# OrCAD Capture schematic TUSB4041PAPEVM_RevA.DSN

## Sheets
1 P1_4041: size C; title: TUSB4041PAPEVM; rev: A.0; company: Texas Instruments, CIS/ICP; note: GAGGIA.DSN
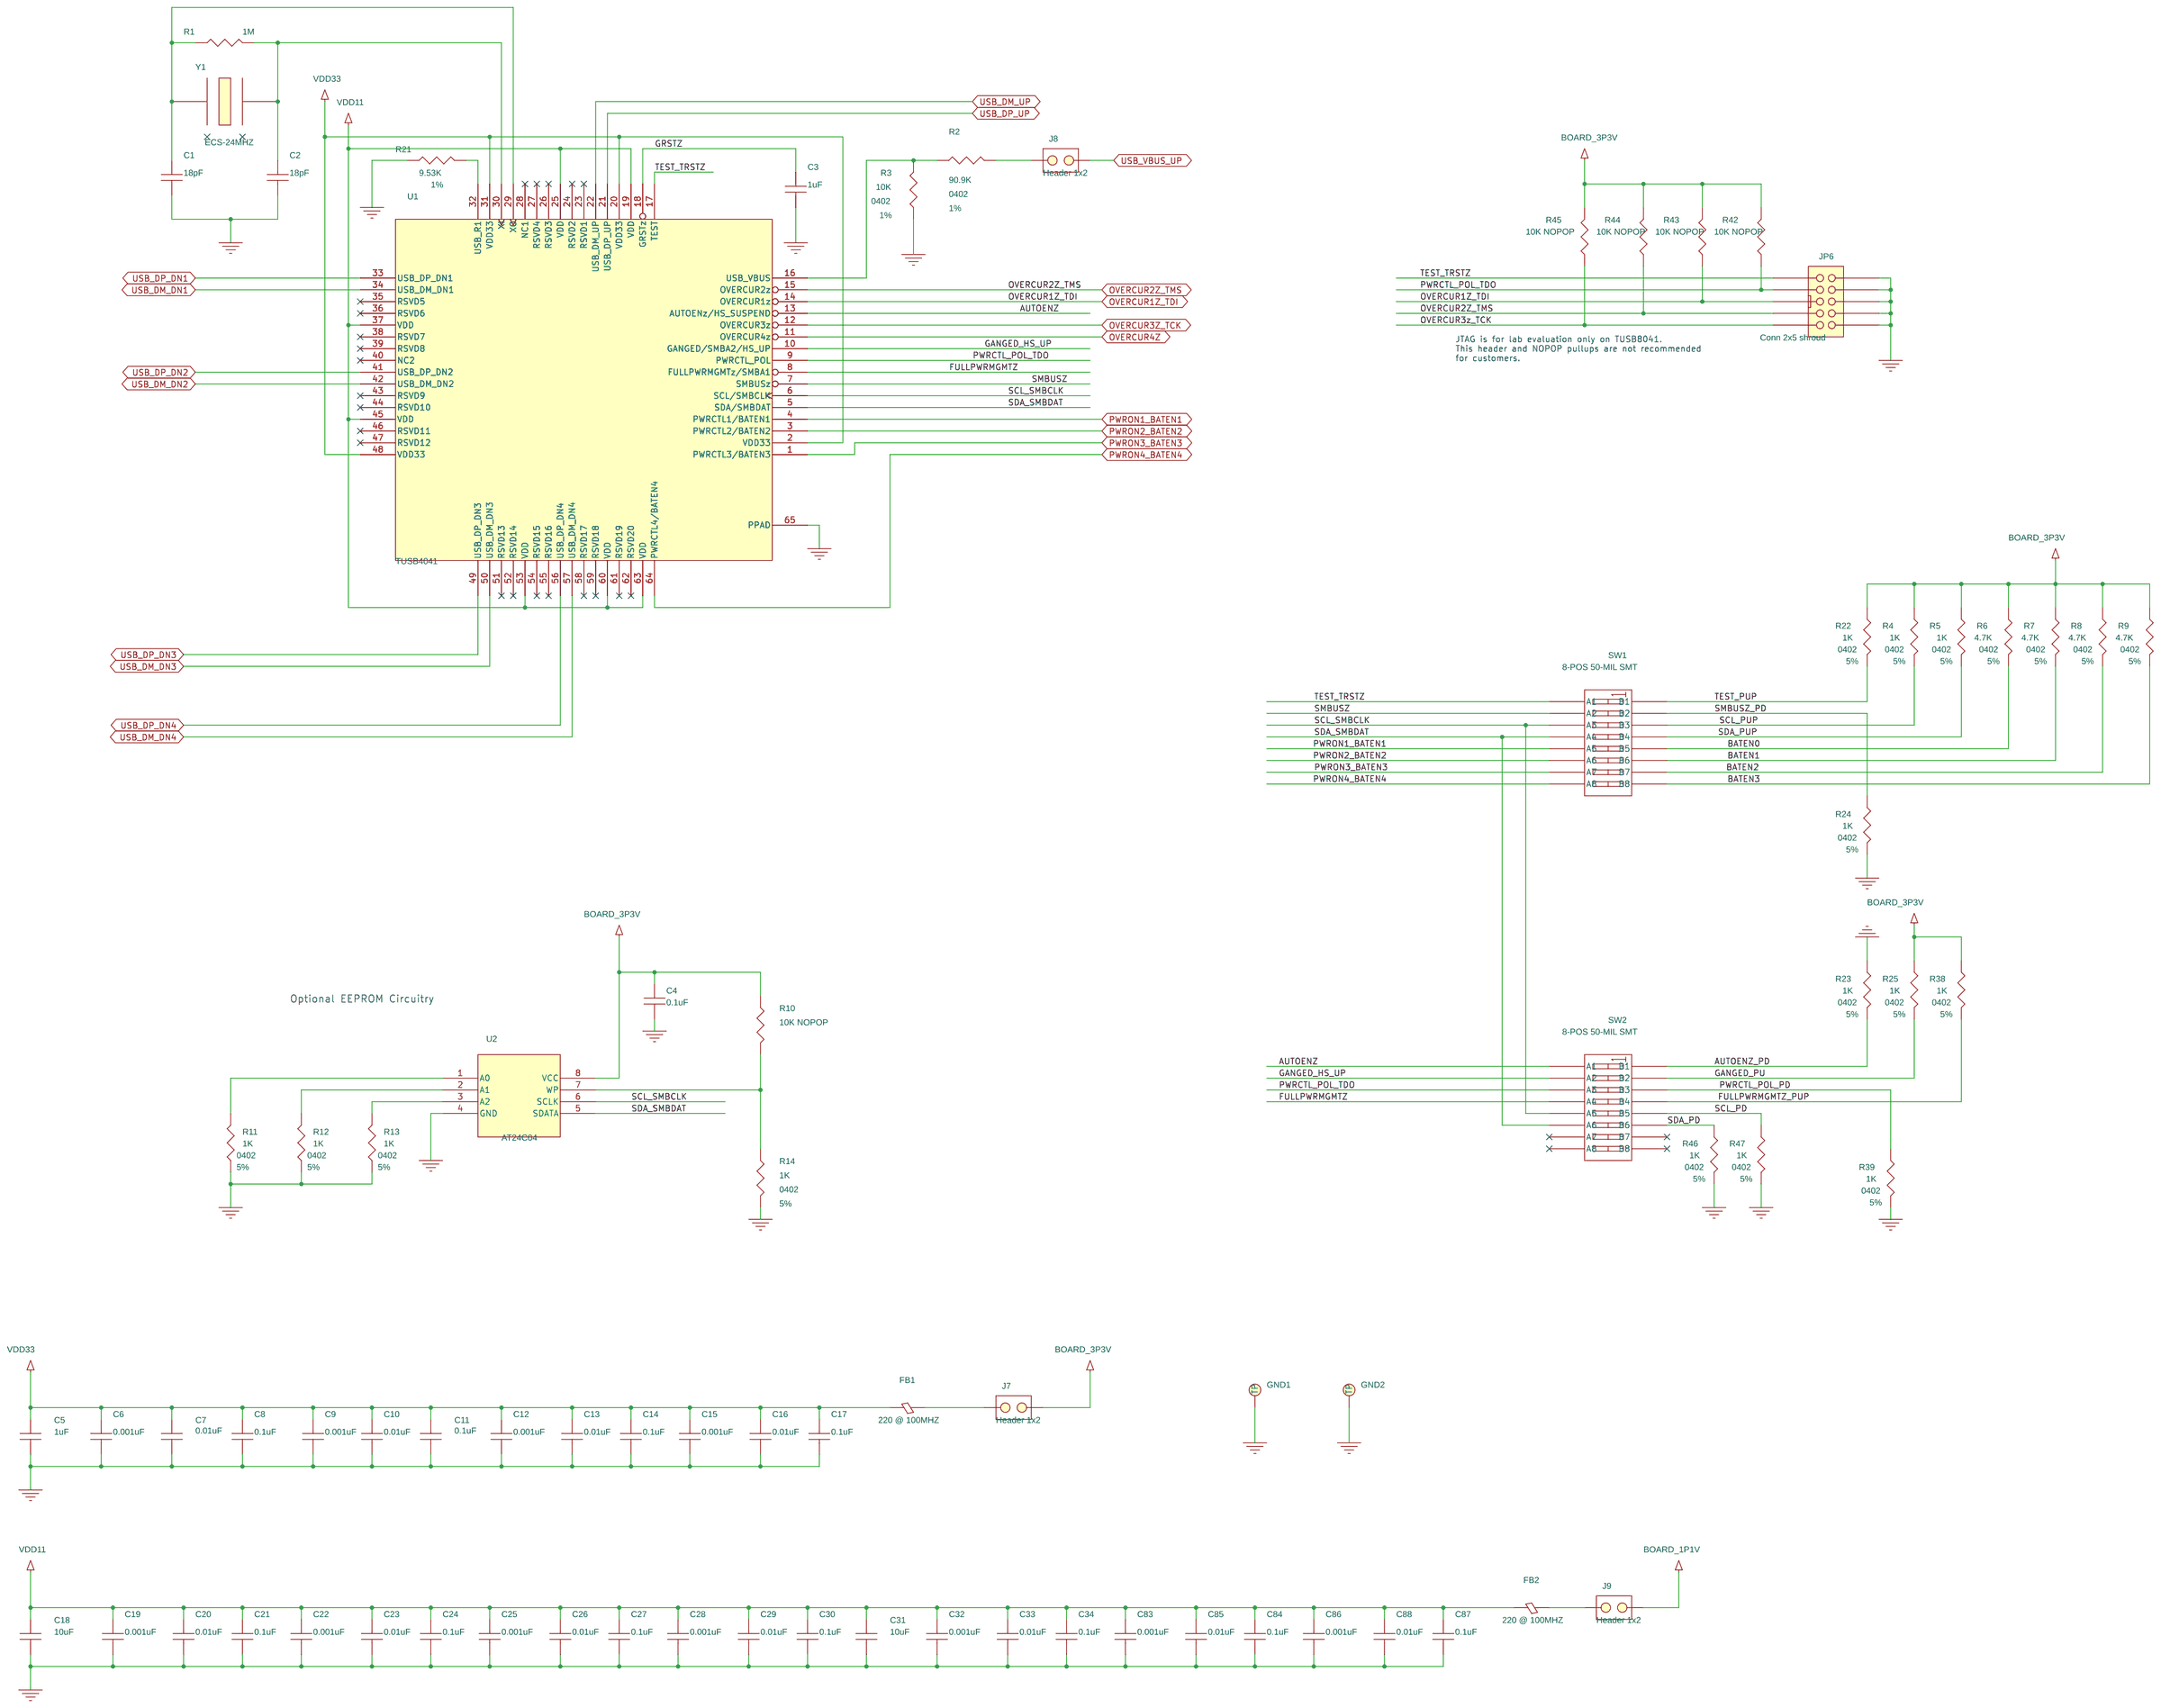
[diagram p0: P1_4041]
2 P2_CONNECTORS: size C; title: TUSB4041PAPEVM: USB2 CONNECTORS
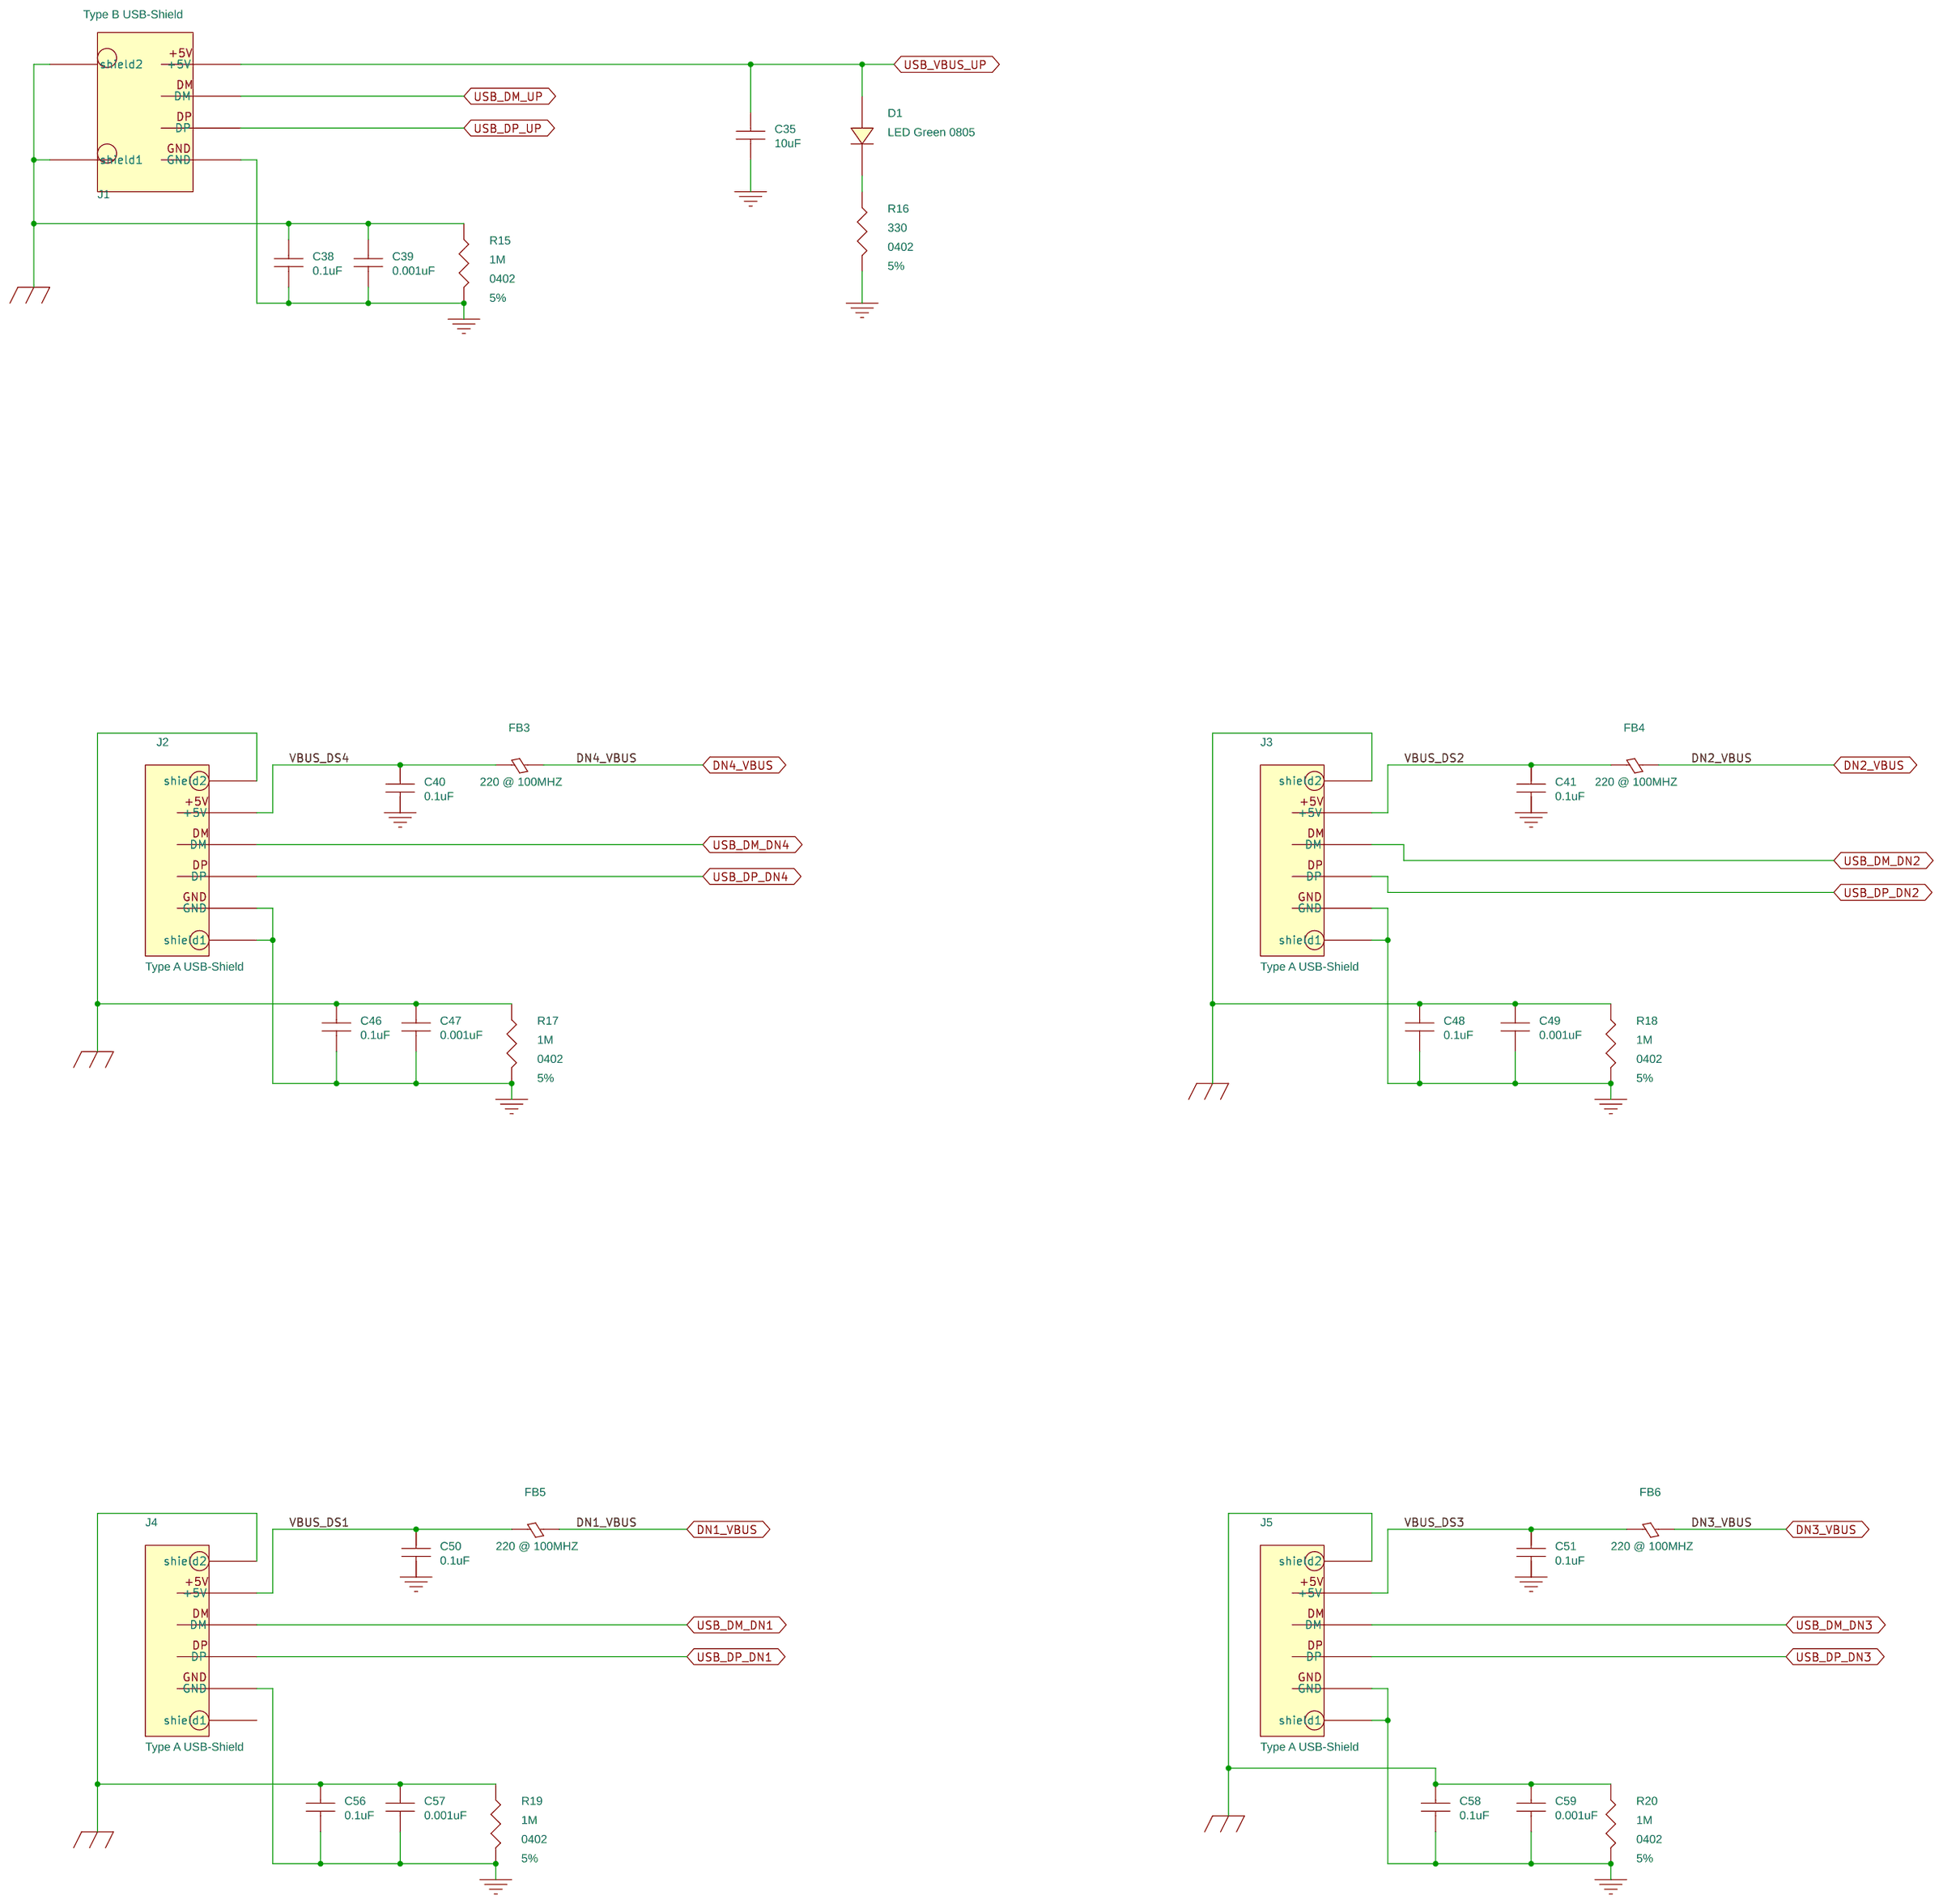
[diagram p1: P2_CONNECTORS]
3 P3_POWER: size C; title: TUSB4041PAPEVM:POWER
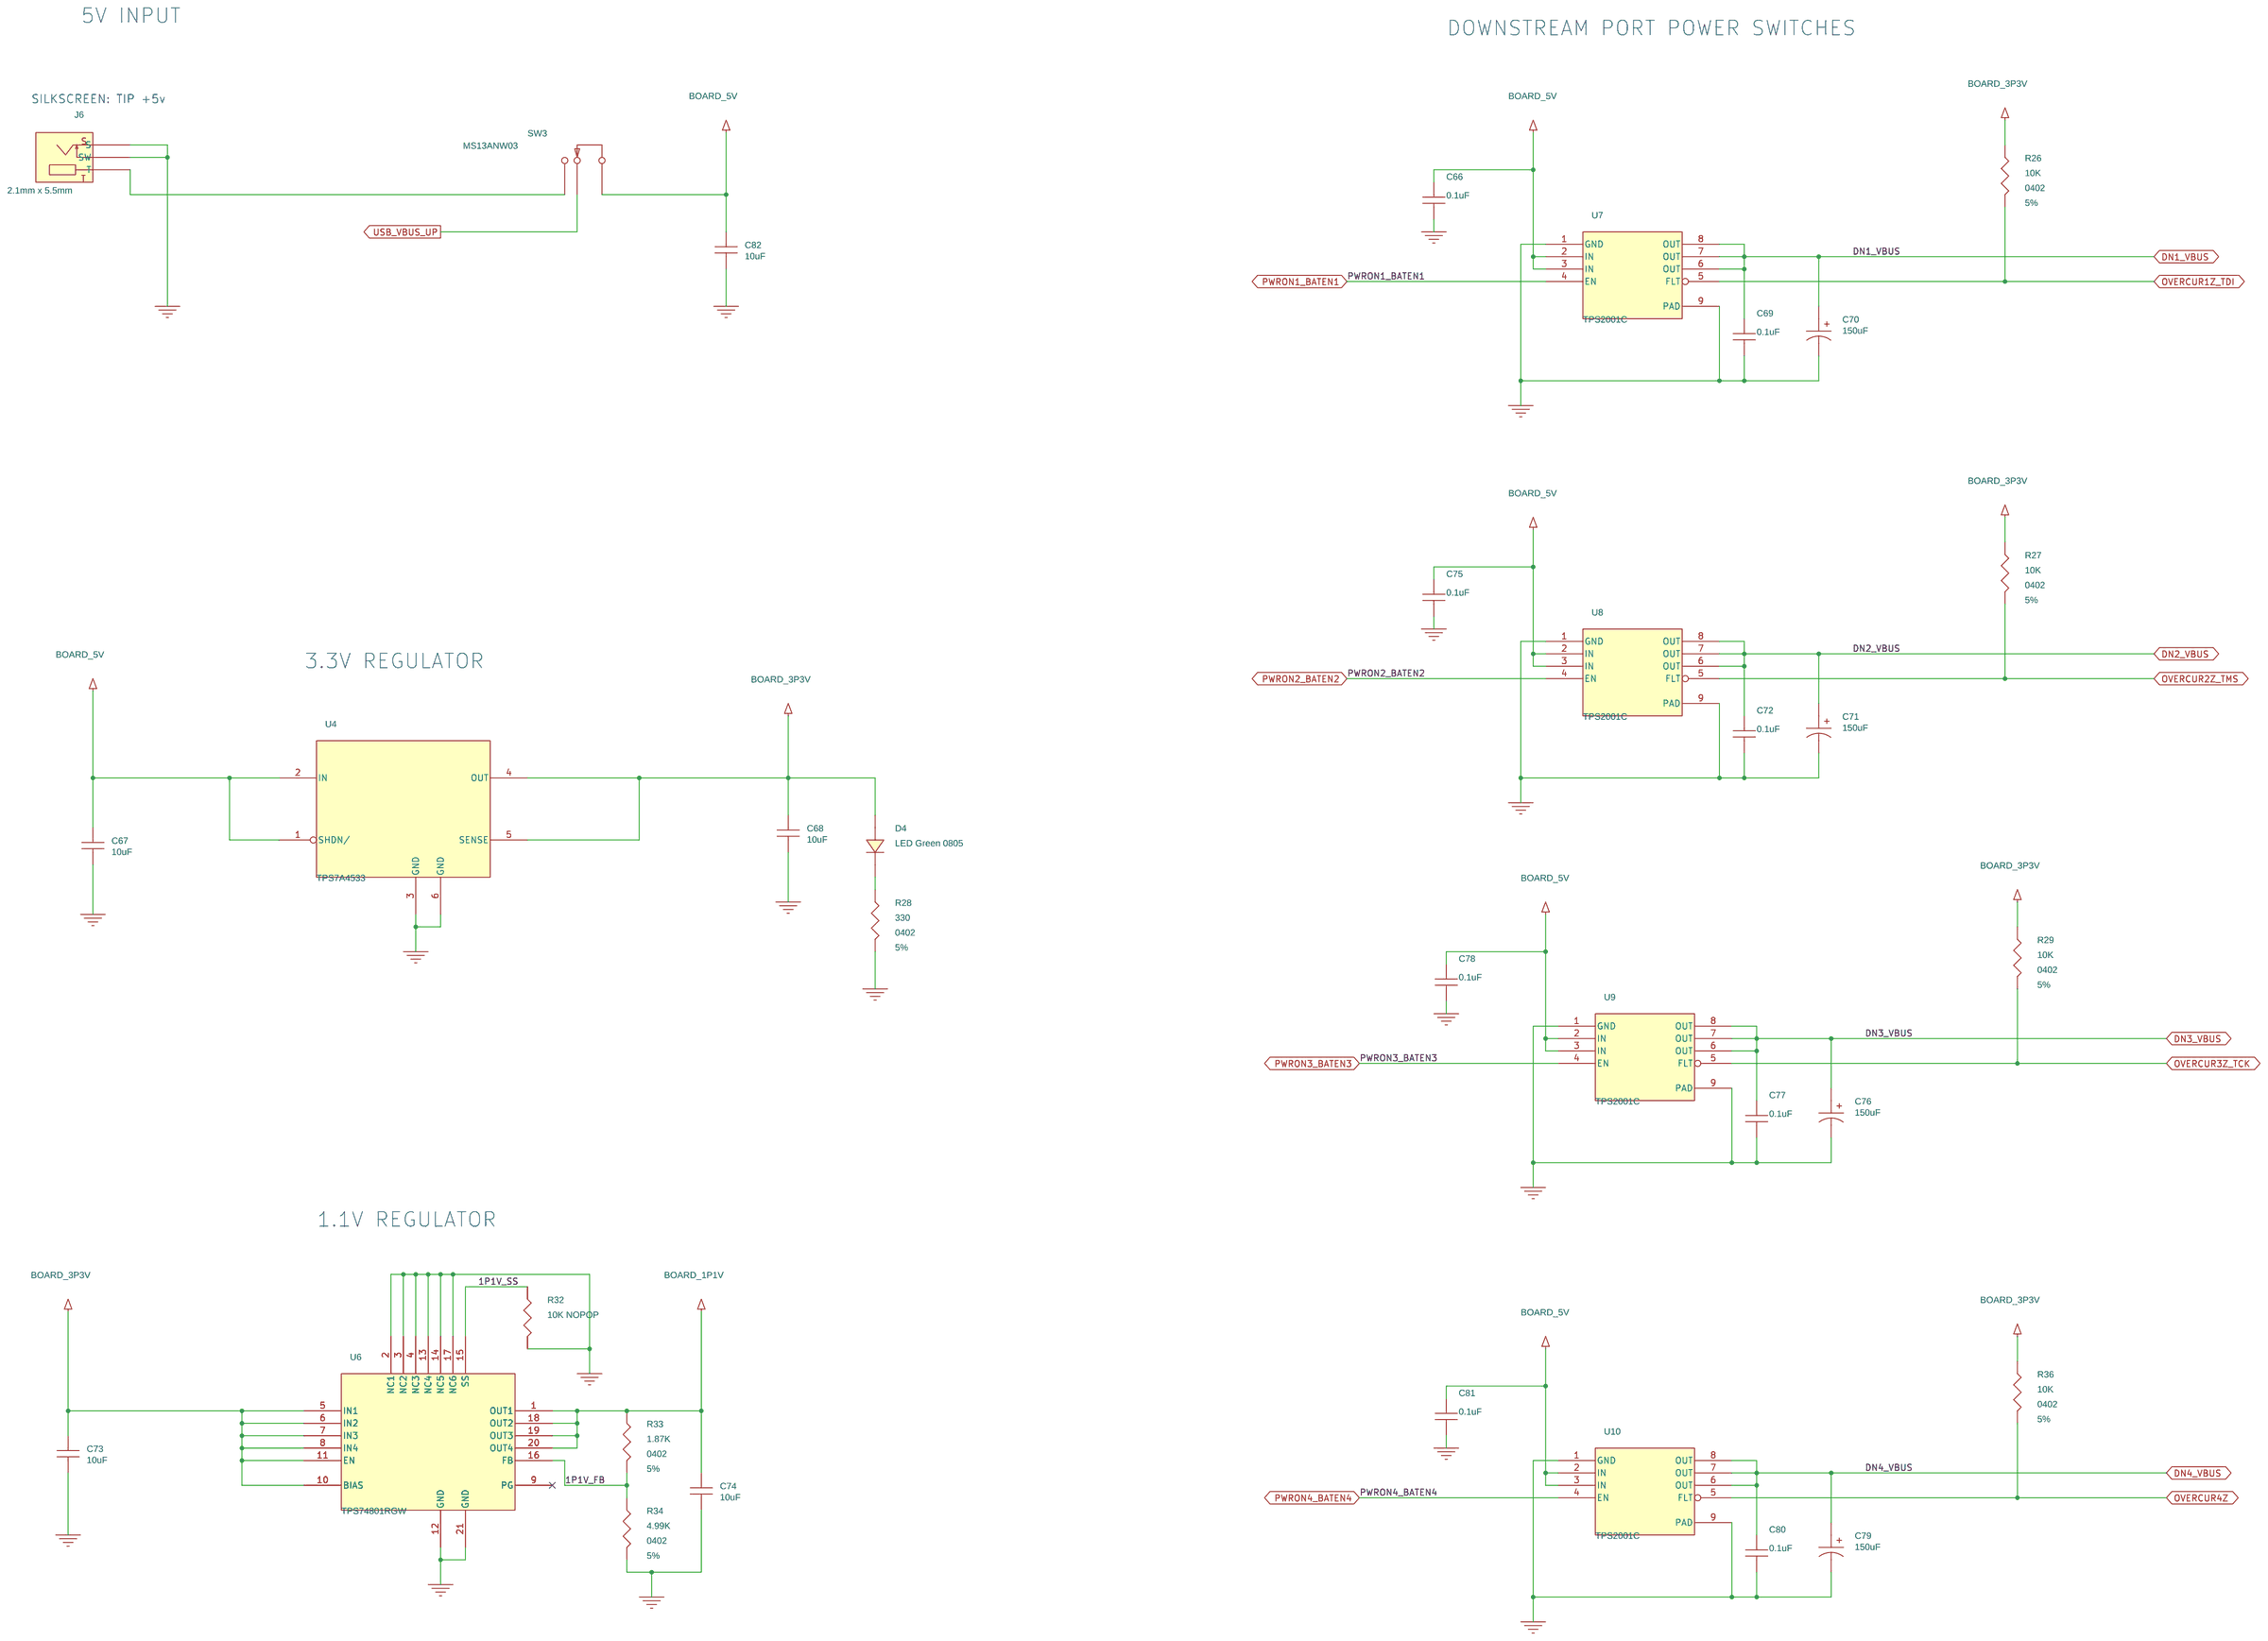
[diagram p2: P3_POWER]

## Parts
sheet P1_4041
C1  18pF  [0402]
C2  18pF  [0402]
C3  1uF  [0402]
C4  0.1uF  [0402]
C5  1uF  [0805]
C6  0.001uF  [0201]
C7  0.01uF  [0201]
C8  0.1uF  [0201]
C9  0.001uF  [0201]
C10  0.01uF  [0201]
C11  0.1uF  [0201]
C12  0.001uF  [0201]
C13  0.01uF  [0201]
C14  0.1uF  [0201]
C15  0.001uF  [0201]
C16  0.01uF  [0201]
C17  0.1uF  [0201]
C18  10uF  [1206]
C19  0.001uF  [0201]
C20  0.01uF  [0201]
C21  0.1uF  [0201]
C22  0.001uF  [0201]
C23  0.01uF  [0201]
C24  0.1uF  [0201]
C25  0.001uF  [0201]
C26  0.01uF  [0201]
C27  0.1uF  [0201]
C28  0.001uF  [0201]
C29  0.01uF  [0201]
C30  0.1uF  [0201]
C31  10uF  [1206]
C32  0.001uF  [0201]
C33  0.01uF  [0201]
C34  0.1uF  [0201]
C83  0.001uF  [0201]
C84  0.1uF  [0201]
C85  0.01uF  [0201]
C86  0.001uF  [0201]
C87  0.1uF  [0201]
C88  0.01uF  [0201]
FB1  220 @ 100MHZ  [0603]
FB2  220 @ 100MHZ  [0603]
GND1  TEST POINT  [testloop]
GND2  TEST POINT  [testloop]
J7  Header 1x2  [HDR_2X1]
J8  Header 1x2  [HDR_2X1]
J9  Header 1x2  [HDR_2X1]
JP6  Conn 2x5 shroud  [eprt-conn-00002-0001]
R1  1M  [0402]
R2  90.9K  [0402]
R3  10K  [0402]
R4  1K  [0402]
R5  1K  [0402]
R6  4.7K  [0402]
R7  4.7K  [0402]
R8  4.7K  [0402]
R9  4.7K  [0402]
R10  10K NOPOP  [0402]
R11  1K  [0402]
R12  1K  [0402]
R13  1K  [0402]
R14  1K  [0402]
R21  9.53K  [0402]
R22  1K  [0402]
R23  1K  [0402]
R24  1K  [0402]
R25  1K  [0402]
R38  1K  [0402]
R39  1K  [0402]
R42  10K NOPOP  [0402]
R43  10K NOPOP  [0402]
R44  10K NOPOP  [0402]
R45  10K NOPOP  [0402]
R46  1K  [0402]
R47  1K  [0402]
SW1  8-POS 50-MIL SMT  [TDA08H0SK1]
SW2  8-POS 50-MIL SMT  [TDA08H0SK1]
U1  TUSB4041  [ironwood_64pin_qfe_7001]
U2  AT24C04  [dip8]
Y1  ECS-24MHZ  [ECX-53B]
sheet P2_CONNECTORS
C35  10uF  [1206]
C38  0.1uF  [0402]
C39  0.001uF  [0402]
C40  0.1uF  [0402]
C41  0.1uF  [0402]
C46  0.1uF  [0402]
C47  0.001uF  [0402]
C48  0.1uF  [0402]
C49  0.001uF  [0402]
C50  0.1uF  [0402]
C51  0.1uF  [0402]
C56  0.1uF  [0402]
C57  0.001uF  [0402]
C58  0.1uF  [0402]
C59  0.001uF  [0402]
D1  LED Green 0805  [0805]
FB3  220 @ 100MHZ  [0603]
FB4  220 @ 100MHZ  [0603]
FB5  220 @ 100MHZ  [0603]
FB6  220 @ 100MHZ  [0603]
J1  Type B USB-Shield  [usbconn_type_b]
J2  Type A USB-Shield  [usbconn_type_a]
J3  Type A USB-Shield  [usbconn_type_a]
J4  Type A USB-Shield  [usbconn_type_a]
J5  Type A USB-Shield  [usbconn_type_a]
R15  1M  [0402]
R16  330  [0402]
R17  1M  [0402]
R18  1M  [0402]
R19  1M  [0402]
R20  1M  [0402]
sheet P3_POWER
C66  0.1uF  [0402]
C67  10uF  [1206]
C68  10uF  [1206]
C69  0.1uF  [0402]
C70  150uF  [7343]
C71  150uF  [7343]
C72  0.1uF  [0402]
C73  10uF  [1206]
C74  10uF  [1206]
C75  0.1uF  [0402]
C76  150uF  [7343]
C77  0.1uF  [0402]
C78  0.1uF  [0402]
C79  150uF  [7343]
C80  0.1uF  [0402]
C81  0.1uF  [0402]
C82  10uF  [1206]
D4  LED Green 0805  [0805]
J6  2.1mm x 5.5mm  [PJ-202AH]
R26  10K  [0402]
R27  10K  [0402]
R28  330  [0402]
R29  10K  [0402]
R32  10K NOPOP  [0402]
R33  1.87K  [0402]
R34  4.99K  [0402]
R36  10K  [0402]
SW3  MS13ANW03  [sw_3pin_spdt]
U4  TPS7A4533  [KTT_6pin]
U6  TPS74801RGW  [RGW20]
U7  TPS2001C  [dgn8]
U8  TPS2001C  [dgn8]
U9  TPS2001C  [dgn8]
U10  TPS2001C  [dgn8]

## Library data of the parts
C1-C35 C38-C41 C46-C51 C56-C59 C66-C69 C72-C75 C77 C78 C80-C88 = CAP_NP
FB1-FB6 = FERRITE_BEAD: Device: BEAD1806; MFC: MuRata; Manuf: MuRata; Manuf PN: BLM18EG221SN1D; Part Number: BLM18EG221SN1D; Part#: BLM18EG221SN1D
GND1 GND2 = Test_Point_Small
J7-J9 = HDR2X1_M_.1
JP6 = eprt-conn-00002-0000: Manuf: 3M; Manuf PN: 2510-6003UB; Manufacturer: 3M; Manufacturer's Part#: 2510-6003UB; PART_NUMBER: DRY2JTAG_3P3; Part#: eprt-conn-00002-0002; TI_Silktext: DRY2JTAG_3P3
R1 R4-R20 R22-R29 R32-R34 R36 R38 R39 R42-R47 = R: Tolerance: 5%
R2 R3 R21 = R: Tolerance: 1%
SW1 SW2 = SW_DIP-8_SM_0: Manuf: C&K(ITT-CANNON); Manuf PN: TDA08H0SK1R; Vendor: C&K (ITT-CANNON); Vendor Part Number: TDA08H0SK1R
U1 = TUSB4041RGC: Manufacturer: Texas Instruments
U2 = AT24C04
Y1 = ECS-25MHZ
D1 D4 = DIODE: Manuf: Lumex; Manuf PN: SML-LX0805GC-TR
J1 = TypeB_USB-Shield_0: Part Number: 609-3656-ND; Vendor: Digi-Key
J2-J5 = TypeA_USB-Shield_0
C70 C71 C76 C79 = CAPACITOR_POL: Manuf: Kemet
J6 = BNC_2: MANUF: CUI STACK; PART_NUMBER: 5V_SUPPLY; TI_Silktext: 5V_SUPPLY
SW3 = SW_SLIDE-SPDT_0: Manuf: NKK Switches
U4 = TPS79633KTT_2: Manuf PN: TPS79633KTT
U6 = TPS74801RGW_1
U7-U10 = TPS2560DRC_3

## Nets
GND: C1.2 C2.2 C3.2 C4.2 C5.2 C6.2 C7.2 C8.2 C9.2 C10.2 C11.2 C12.2 C13.2 C14.2 C15.2 C16.2 C17.2 C18.2 C19.2 C20.2 C21.2 C22.2 C23.2 C24.2 C25.2 C26.2 C27.2 C28.2 C29.2 C30.2 C31.2 C32.2 C33.2 C34.2 C35.2 C38.2 C39.2 C40.2 C41.2 C46.2 C47.2 C48.2 C49.2 C50.2 C51.2 C56.2 C57.2 C58.2 C59.2 C66.2 C67.2 C68.2 C69.2 C70.2 C71.2 C72.2 C73.2 C74.2 C75.2 C76.2 C77.2 C78.2 C79.2 C80.2 C81.2 C82.2 C83.2 C84.2 C85.2 C86.2 C87.2 C88.2 GND1.1(TP) GND2.1(TP) J1.4(GND) J2.4(GND) J2.7(shield1) J3.4(GND) J3.7(shield1) J4.4(GND) J5.4(GND) J5.7(shield1) J6.2(S) J6.3(SW) JP6.2 JP6.4 JP6.6 JP6.8 JP6.10 R3.2 R11.1 R12.1 R13.1 R14.2 R15.2 R16.2 R17.2 R18.2 R19.2 R20.2 R21.1 R23.2 R24.1 R28.2 R32.2 R34.2 R39.1 R46.1 R47.1 U1.65(PPAD) U2.4(GND) U4.3(GND) U4.6(GND) U6.2(NC1) U6.3(NC2) U6.4(NC3) U6.12(GND) U6.13(NC4) U6.14(NC5) U6.17(NC6) U6.21(GND) U7.1(GND) U7.9(PAD) U8.1(GND) U8.9(PAD) U9.1(GND) U9.9(PAD) U10.1(GND) U10.9(PAD)
GND_EARTH: C38.1 C39.1 C46.1 C47.1 C48.1 C49.1 C56.1 C57.1 C58.1 C59.1 J1.7(shield2) J1.8(shield1) J2.8(shield2) J3.8(shield2) J4.8(shield2) J5.8(shield2) R15.1 R17.1 R18.1 R19.1 R20.1
VBUS_DS1: C50.1 FB5.1 J4.1(+5V)
VBUS_DS2: C41.1 FB4.1 J3.1(+5V)
VBUS_DS3: C51.1 FB6.1 J5.1(+5V)
VBUS_DS4: C40.1 FB3.1 J2.1(+5V)
VDD11: C18.1 C19.1 C20.1 C21.1 C22.1 C23.1 C24.1 C25.1 C26.1 C27.1 C28.1 C29.1 C30.1 C31.1 C32.1 C33.1 C34.1 C83.1 C84.1 C85.1 C86.1 C87.1 C88.1 FB2.1 U1.19(VDD) U1.25(VDD) U1.37(VDD) U1.45(VDD) U1.53(VDD) U1.60(VDD) U1.63(VDD)
VDD33: C5.1 C6.1 C7.1 C8.1 C9.1 C10.1 C11.1 C12.1 C13.1 C14.1 C15.1 C16.1 C17.1 FB1.1 U1.2(VDD33) U1.20(VDD33) U1.31(VDD33) U1.48(VDD33)
1P1V_FB: R33.2 R34.1 U6.16(FB)
1P1V_SS: R32.1 U6.15(SS)
AUTOENZ: SW2.1(A1) U1.13(AUTOENz/HS_SUSPEND)
AUTOENZ_PD: R23.1 SW2.16(B1)
BATEN0: R6.1 SW1.12(B5)
BATEN1: R7.1 SW1.11(B6)
BATEN2: R8.1 SW1.10(B7)
BATEN3: R9.1 SW1.9(B8)
BOARD_1P1V: C74.1 J9.2 R33.1 U6.1(OUT1) U6.18(OUT2) U6.19(OUT3) U6.20(OUT4)
BOARD_3P3V: C4.1 C68.1 C73.1 D4.1(A) J7.2 R4.2 R5.2 R6.2 R7.2 R8.2 R9.2 R10.1 R22.2 R25.2 R26.1 R27.1 R29.1 R36.1 R38.2 R42.1 R43.1 R44.1 R45.1 U2.8(VCC) U4.4(OUT) U4.5(SENSE) U6.5(IN1) U6.6(IN2) U6.7(IN3) U6.8(IN4) U6.10(BIAS) U6.11(EN)
BOARD_5V: C66.1 C67.1 C75.1 C78.1 C81.1 C82.1 SW3.2 U4.1(SHDN/) U4.2(IN) U7.2(IN) U7.3(IN) U8.2(IN) U8.3(IN) U9.2(IN) U9.3(IN) U10.2(IN) U10.3(IN)
DN1_VBUS: C69.1 C70.1 FB5.2 U7.6(OUT) U7.7(OUT) U7.8(OUT)
DN2_VBUS: C71.1 C72.1 FB4.2 U8.6(OUT) U8.7(OUT) U8.8(OUT)
DN3_VBUS: C76.1 C77.1 FB6.2 U9.6(OUT) U9.7(OUT) U9.8(OUT)
DN4_VBUS: C79.1 C80.1 FB3.2 U10.6(OUT) U10.7(OUT) U10.8(OUT)
FULLPWRMGMTZ: SW2.4(A4) U1.8(FULLPWRMGMTz/SMBA1)
FULLPWRMGMTZ_PUP: R38.1 SW2.13(B4)
GANGED_HS_UP: SW2.2(A2) U1.10(GANGED/SMBA2/HS_UP)
GANGED_PU: R25.1 SW2.15(B2)
GRSTZ: C3.1 U1.18(GRSTz)
OVERCUR1Z_TDI: JP6.5 R26.2 R43.2 U1.14(OVERCUR1z) U7.5(FLT)
OVERCUR2Z_TMS: JP6.7 R27.2 R44.2 U1.15(OVERCUR2z) U8.5(FLT)
OVERCUR3Z_TCK: JP6.9 R29.2 R45.2 U1.12(OVERCUR3z) U9.5(FLT)
OVERCUR4Z: R36.2 U1.11(OVERCUR4z) U10.5(FLT)
PWRCTL_POL_PD: R39.2 SW2.14(B3)
PWRCTL_POL_TDO: JP6.3 R42.2 SW2.3(A3) U1.9(PWRCTL_POL)
PWRON1_BATEN1: SW1.5(A5) U1.4(PWRCTL1/BATEN1) U7.4(EN)
PWRON2_BATEN2: SW1.6(A6) U1.3(PWRCTL2/BATEN2) U8.4(EN)
PWRON3_BATEN3: SW1.7(A7) U1.1(PWRCTL3/BATEN3) U9.4(EN)
PWRON4_BATEN4: SW1.8(A8) U1.64(PWRCTL4/BATEN4) U10.4(EN)
SCL_PD: R47.2 SW2.12(B5)
SCL_PUP: R4.1 SW1.14(B3)
SCL_SMBCLK: SW1.3(A3) SW2.5(A5) U1.6(SCL/SMBCLK) U2.6(SCLK)
SDA_PD: R46.2 SW2.11(B6)
SDA_PUP: R5.1 SW1.13(B4)
SDA_SMBDAT: SW1.4(A4) SW2.6(A6) U1.5(SDA/SMBDAT) U2.5(SDATA)
SMBUSZ: SW1.2(A2) U1.7(SMBUSz)
SMBUSZ_PD: R24.2 SW1.15(B2)
TEST_PUP: R22.1 SW1.16(B1)
TEST_TRSTZ: JP6.1 SW1.1(A1) U1.17(TEST)
USB_DM_DN1: J4.2(DM) U1.34(USB_DM_DN1)
USB_DM_DN2: J3.2(DM) U1.42(USB_DM_DN2)
USB_DM_DN3: J5.2(DM) U1.50(USB_DM_DN3)
USB_DM_DN4: J2.2(DM) U1.57(USB_DM_DN4)
USB_DM_UP: J1.2(DM) U1.22(USB_DM_UP)
USB_DP_DN1: J4.3(DP) U1.33(USB_DP_DN1)
USB_DP_DN2: J3.3(DP) U1.41(USB_DP_DN2)
USB_DP_DN3: J5.3(DP) U1.49(USB_DP_DN3)
USB_DP_DN4: J2.3(DP) U1.56(USB_DP_DN4)
USB_DP_UP: J1.3(DP) U1.21(USB_DP_UP)
USB_VBUS_UP: C35.1 D1.1(A) J1.1(+5V) J8.2 SW3.1
N17052812: R2.1 R3.1 U1.16(USB_VBUS)
N17181221: R10.2 R14.1 U2.7(WP)
N17181233: R11.2 U2.1(A0)
N17181243: R12.2 U2.2(A1)
N17181324: R13.2 U2.3(A2)
N17383170: D1.2(K) R16.1
N17408350: D4.2(K) R28.1
N18334081: C2.1 R1.2 U1.30(XI) Y1.3(a3)
N18334093: C1.1 R1.1 U1.29(XO) Y1.1(a1)
N18713919: R21.2 U1.32(USB_R1)
N18725733: J8.1 R2.2
N18726136: FB1.2 J7.1
N18726182: FB2.2 J9.1
N18885098: J6.1(T) SW3.3

Not connected (* = marked no-connect by the designer): J4 7(shield1); SW2 7(A7)* 8(A8)* 9(B8)* 10(B7)*; U1 23(RSVD1)* 24(RSVD2)* 26(RSVD3)* 27(RSVD4)* 28(NC1)* 35(RSVD5)* 36(RSVD6)* 38(RSVD7)* 39(RSVD8)* 40(NC2)* 43(RSVD9)* 44(RSVD10)* 46(RSVD11)* 47(RSVD12)* 51(RSVD13)* 52(RSVD14)* 54(RSVD15)* 55(RSVD16)* 58(RSVD17)* 59(RSVD18)* 61(RSVD19)* 62(RSVD20)*; U6 9(PG)*; Y1 2(a2)* 4(a4)*

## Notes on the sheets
sheet 1
- JTAG is for lab evaluation only on TUSB8041.
  This header and NOPOP pullups are not recommended
  for customers.
- Optional EEPROM Circuitry
sheet 3
- 5V INPUT
- DOWNSTREAM PORT POWER SWITCHES
- SILKSCREEN: TIP +5v
- 3.3V REGULATOR
- 1.1V REGULATOR
